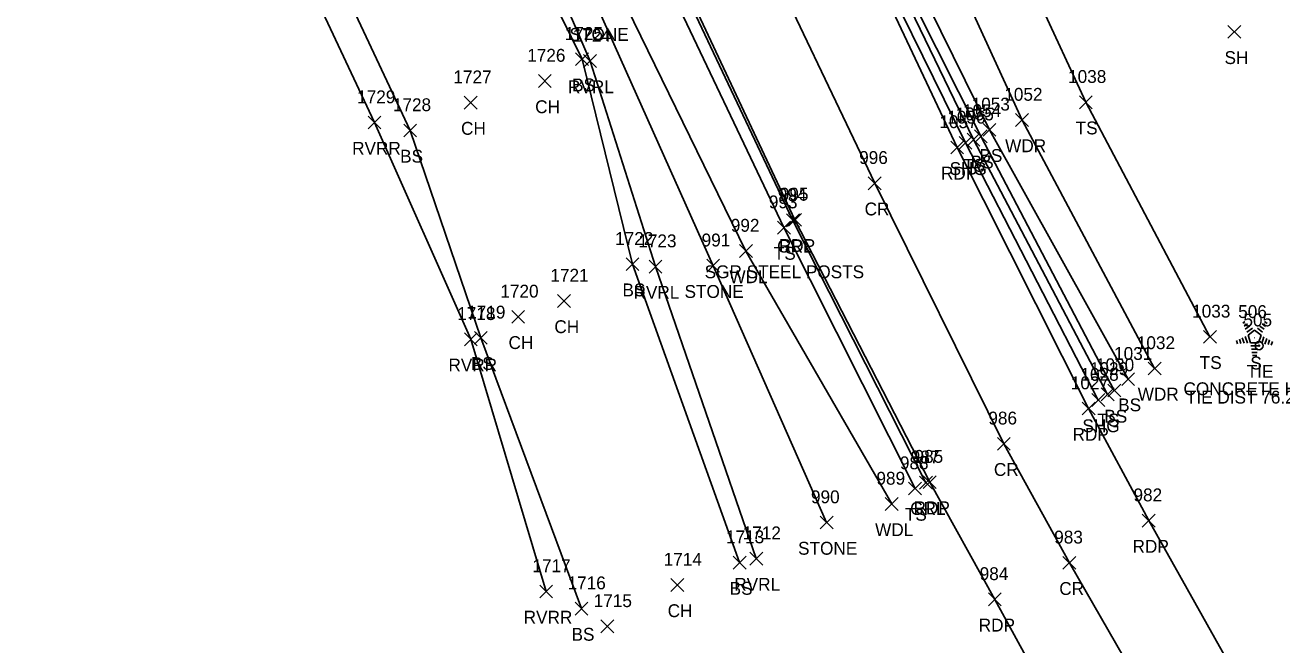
# Model space of a CAD drawing. Extents: x 1545627 to 1546562, y 571176 to 576667.
# Drawn here: x 1546177.9 to 1546373.5, y 571495.7 to 571592.1 of the extents above; entities that cross this region are included whole.
import ezdxf

# ---------------------------------------------------------------- set-up
doc = ezdxf.new("R2010")
doc.units = 0
for name, color, linetype in [('C_A', 7, 'Continuous'), ('C_C', 7, 'Continuous'), ('C_I', 7, 'Continuous'), ('CBP', 7, 'Continuous'), ('L_A', 7, 'Continuous'), ('L_C', 7, 'Continuous'), ('L_I', 7, 'Continuous'), ('L_TIC', 7, 'Continuous'), ('LASF', 7, 'Continuous'), ('LAWA', 7, 'Continuous'), ('LAWE', 7, 'Continuous'), ('LELB', 7, 'Continuous'), ('LTC', 7, 'Continuous'), ('P_A', 7, 'Continuous'), ('P_I', 7, 'Continuous'), ('P_TIC', 7, 'Continuous'), ('PET', 7, 'Continuous'), ('PRC', 7, 'Continuous'), ('PSU', 7, 'Continuous'), ('R_A', 7, 'Continuous'), ('R_C', 7, 'Continuous'), ('R_I', 7, 'Continuous'), ('R_TIC', 7, 'Continuous'), ('RGR', 7, 'Continuous')]:
    doc.layers.add(name, color=color, linetype=linetype)

msp = doc.modelspace()

# ---------------------------------------------------------------- linework, layer by layer
at = {"layer": 'CBP'}
for radius in [0.625, 0.0833]:
    msp.add_circle((1546369.94, 571542.21), radius, dxfattribs=at)
at = {"layer": 'L_TIC'}
for points in [[(1546365.08, 571590.01), (1546367.08, 571592.01)], [(1546367.08, 571590.01), (1546365.08, 571592.01)], [(1546263.55, 571585.76), (1546265.55, 571587.76)], [(1546265.55, 571585.76), (1546263.55, 571587.76)], [(1546264.8, 571585.47), (1546266.8, 571587.47)], [(1546266.8, 571585.47), (1546264.8, 571587.47)], [(1546257.77, 571582.37), (1546259.77, 571584.37)], [(1546259.77, 571582.37), (1546257.77, 571584.37)], [(1546246.23, 571579.01), (1546248.23, 571581.01)], [(1546248.23, 571579.01), (1546246.23, 571581.01)], [(1546341.98, 571579.07), (1546343.98, 571581.07)], [(1546343.98, 571579.07), (1546341.98, 571581.07)], [(1546332.05, 571576.3), (1546334.05, 571578.3)], [(1546334.05, 571576.3), (1546332.05, 571578.3)], [(1546231.25, 571575.91), (1546233.25, 571577.91)], [(1546233.25, 571575.91), (1546231.25, 571577.91)], [(1546236.8, 571574.68), (1546238.8, 571576.68)], [(1546238.8, 571574.68), (1546236.8, 571576.68)], [(1546326.97, 571574.78), (1546328.97, 571576.78)], [(1546328.97, 571574.78), (1546326.97, 571576.78)], [(1546324.48, 571573.25), (1546326.48, 571575.25)], [(1546326.48, 571573.25), (1546324.48, 571575.25)], [(1546325.62, 571573.77), (1546327.62, 571575.77)], [(1546327.62, 571573.77), (1546325.62, 571575.77)], [(1546294.99, 571559.57), (1546296.99, 571561.57)], [(1546296.99, 571559.57), (1546294.99, 571561.57)], [(1546289.07, 571555.93), (1546291.07, 571557.93)], [(1546291.07, 571555.93), (1546289.07, 571557.93)], [(1546271.41, 571553.88), (1546273.41, 571555.88)], [(1546273.41, 571553.88), (1546271.41, 571555.88)], [(1546275, 571553.51), (1546277, 571555.51)], [(1546277, 571553.51), (1546275, 571555.51)], [(1546283.96, 571553.64), (1546285.96, 571555.64)], [(1546285.96, 571553.64), (1546283.96, 571555.64)], [(1546260.76, 571548.16), (1546262.76, 571550.16)], [(1546262.76, 571548.16), (1546260.76, 571550.16)], [(1546253.62, 571545.69), (1546255.62, 571547.69)], [(1546255.62, 571545.69), (1546253.62, 571547.69)], [(1546246.25, 571542.2), (1546248.25, 571544.2)], [(1546248.25, 571542.2), (1546246.25, 571544.2)], [(1546247.81, 571542.43), (1546249.81, 571544.43)], [(1546249.81, 571542.43), (1546247.81, 571544.43)], [(1546361.29, 571542.58), (1546363.29, 571544.58)], [(1546363.29, 571542.58), (1546361.29, 571544.58)], [(1546352.68, 571537.67), (1546354.68, 571539.67)], [(1546354.68, 571537.67), (1546352.68, 571539.67)], [(1546348.57, 571536), (1546350.57, 571538)], [(1546350.57, 571536), (1546348.57, 571538)], [(1546345.37, 571533.64), (1546347.37, 571535.64)], [(1546347.37, 571533.64), (1546345.37, 571535.64)], [(1546346.4, 571534.24), (1546348.4, 571536.24)], [(1546348.4, 571534.24), (1546346.4, 571536.24)], [(1546315.39, 571518.99), (1546317.39, 571520.99)], [(1546317.39, 571518.99), (1546315.39, 571520.99)], [(1546311.75, 571516.59), (1546313.75, 571518.59)], [(1546313.75, 571516.59), (1546311.75, 571518.59)], [(1546301.63, 571513.7), (1546303.63, 571515.7)], [(1546303.63, 571513.7), (1546301.63, 571515.7)], [(1546290.68, 571508.09), (1546292.68, 571510.09)], [(1546292.68, 571508.09), (1546290.68, 571510.09)], [(1546288.09, 571507.47), (1546290.09, 571509.47)], [(1546290.09, 571507.47), (1546288.09, 571509.47)], [(1546278.39, 571503.99), (1546280.39, 571505.99)], [(1546280.39, 571503.99), (1546278.39, 571505.99)], [(1546257.96, 571502.98), (1546259.96, 571504.98)], [(1546259.96, 571502.98), (1546257.96, 571504.98)], [(1546263.48, 571500.32), (1546265.48, 571502.32)], [(1546265.48, 571500.32), (1546263.48, 571502.32)], [(1546267.49, 571497.55), (1546269.49, 571499.55)], [(1546269.49, 571497.55), (1546267.49, 571499.55)]]:
    msp.add_lwpolyline(points, dxfattribs=at)
at = {"layer": 'LASF'}
msp.add_lwpolyline([(1546302.63, 571514.7), (1546284.96, 571554.64), (1546267.07, 571594.62), (1546248.5, 571636.16), (1546232.58, 571676.44), (1546221.39, 571711.67), (1546206.12, 571743.52), (1546187.79, 571777.34), (1546173.69, 571810.79)], dxfattribs=at)
at = {"layer": 'LAWA'}
for points in [[(1546353.68, 571538.67), (1546333.05, 571577.3), (1546316.5, 571613.36), (1546304.35, 571639.71), (1546298.51, 571653.83), (1546282.89, 571690.9), (1546283.41, 571696.03), (1546272.32, 571717.42), (1546269.96, 571722.04), (1546267.97, 571732.31), (1546261.81, 571747.15), (1546257.75, 571780.48), (1546250.52, 571795.52), (1546235.49, 571816.76), (1546225.64, 571844.56)], [(1546312.75, 571517.59), (1546290.07, 571556.93), (1546270.45, 571597.1), (1546251.85, 571637.66), (1546235.21, 571678.3), (1546232.58, 571676.44)]]:
    msp.add_lwpolyline(points, dxfattribs=at)
at = {"layer": 'LAWE'}
for points in [[(1546291.68, 571509.09), (1546276, 571554.51), (1546265.8, 571586.47), (1546246.73, 571630.75), (1546234.82, 571659.95), (1546216.56, 571711.52), (1546198.01, 571746.58), (1546176.48, 571789.7), (1546167.29, 571818.28), (1546149.73, 571861.96), (1546132.38, 571905.18), (1546121.26, 571957.17), (1546118.8, 571996.68)], [(1546258.96, 571503.98), (1546247.25, 571543.2), (1546232.25, 571576.91), (1546212.48, 571618.99), (1546196.14, 571656.31), (1546182.65, 571695.75), (1546160.61, 571737.45), (1546138.23, 571773.59), (1546130.29, 571811.19), (1546113.32, 571843.26), (1546096.49, 571860.06), (1546088.58, 571875.57), (1546087.04, 571900.32), (1546085.16, 571952.92), (1546079.44, 571966.95), (1546077.79, 571985.49)]]:
    msp.add_lwpolyline(points, dxfattribs=at)
at = {"layer": 'LELB'}
for points in [[(1546347.4, 571535.24), (1546326.62, 571574.77), (1546309.35, 571609.13), (1546297.64, 571636.43), (1546292.79, 571646.22), (1546275.73, 571689.36), (1546263.63, 571715.11), (1546250.32, 571751.35), (1546233.4, 571797.16), (1546220.82, 571841.74), (1546218.61, 571853), (1546198.39, 571897.18), (1546185.1, 571947.88), (1546175.65, 571989.22), (1546174.94, 572003.26), (1546174.78, 572026.81), (1546167.55, 572047.44), (1546164.76, 572064.39), (1546160.42, 572092.89), (1546150.12, 572129.23)], [(1546346.37, 571534.64), (1546325.48, 571574.25), (1546308.89, 571608.63), (1546296.21, 571635.99), (1546273.97, 571687.64), (1546262.69, 571714.72), (1546248.75, 571750.39), (1546231.96, 571796.63), (1546217.3, 571838.7), (1546210.36, 571854.99), (1546196.65, 571897), (1546182.1, 571946.81), (1546169.64, 571995.56), (1546168.24, 572028.13), (1546158.04, 572044.97), (1546148.17, 572086.53), (1546140.64, 572120.6)], [(1546316.39, 571519.99), (1546295.99, 571560.57), (1546277.23, 571599.95), (1546257.92, 571640.86), (1546240.42, 571680.68), (1546227.25, 571713.56), (1546212.6, 571746.96), (1546199.61, 571780.81), (1546186.37, 571815.41), (1546174.93, 571851.82), (1546162.84, 571891.38), (1546151.94, 571927.81), (1546142.36, 571967.05), (1546132.26, 572008.4), (1546126.74, 572032.68), (1546118.89, 572071.99), (1546116.87, 572083.76)], [(1546289.09, 571508.47), (1546272.41, 571554.88), (1546264.55, 571586.76), (1546244.35, 571627.87), (1546230.42, 571657.81), (1546213.76, 571710.05), (1546197.12, 571744.15), (1546174.21, 571790.13), (1546160.91, 571814.7), (1546145.83, 571859.21), (1546131.62, 571904.03), (1546118.44, 571956.95), (1546115.97, 571995.99), (1546108.78, 572035.92), (1546103.73, 572068.58)], [(1546264.48, 571501.32), (1546248.81, 571543.43), (1546237.8, 571575.68), (1546217.63, 571618.65), (1546201.94, 571655.46), (1546187.64, 571696.37), (1546165.93, 571736.68), (1546143.43, 571776.5), (1546133.35, 571812.72), (1546115.39, 571843.89), (1546097.02, 571861.67), (1546090.93, 571875.32), (1546090.22, 571893.11)], [(1546362.29, 571543.58), (1546342.98, 571580.07), (1546328.32, 571611.66), (1546309.49, 571653.11), (1546294.54, 571692.89), (1546292.56, 571714.76), (1546278.25, 571725.92)], [(1546349.57, 571537), (1546327.97, 571575.78), (1546310.96, 571610.3), (1546300.23, 571637.22)]]:
    msp.add_lwpolyline(points, dxfattribs=at)
at = {"layer": 'LTC'}
for p, q in [((1546367.39, 571545.71), (1546367.74, 571545.97)), ((1546367.6, 571545.25), (1546368.12, 571545.63)), ((1546367.8, 571544.78), (1546368.51, 571545.29)), ((1546368.01, 571544.32), (1546368.89, 571544.95)), ((1546369.67, 571544.91), (1546370.48, 571544.32)), ((1546370.04, 571545.26), (1546370.72, 571544.76)), ((1546370.41, 571545.61), (1546370.96, 571545.21)), ((1546370.78, 571545.95), (1546371.2, 571545.65)), ((1546366.42, 571542.99), (1546366.57, 571542.52)), ((1546366.87, 571543.21), (1546367.09, 571542.56)), ((1546367.33, 571543.43), (1546367.6, 571542.59)), ((1546367.78, 571543.64), (1546368.12, 571542.62)), ((1546368.24, 571543.86), (1546369.25, 571544.6)), ((1546368.24, 571543.86), (1546368.63, 571542.67)), ((1546369.25, 571544.6), (1546370.25, 571543.87)), ((1546370.25, 571543.87), (1546369.86, 571542.67)), ((1546370.69, 571543.6), (1546370.35, 571542.56)), ((1546371.13, 571543.35), (1546370.84, 571542.46)), ((1546371.57, 571543.1), (1546371.34, 571542.37)), ((1546372.02, 571542.85), (1546371.83, 571542.27)), ((1546369.86, 571542.67), (1546368.63, 571542.67)), ((1546369.82, 571542.17), (1546368.67, 571542.17)), ((1546369.73, 571541.67), (1546368.75, 571541.67)), ((1546369.65, 571541.17), (1546368.82, 571541.17)), ((1546369.57, 571540.67), (1546368.89, 571540.67))]:
    msp.add_line(p, q, dxfattribs=at)
at = {"layer": 'P_TIC'}
for points in [[(1546323.24, 571572.75), (1546325.24, 571574.75)], [(1546325.24, 571572.75), (1546323.24, 571574.75)], [(1546321.94, 571572.04), (1546323.94, 571574.04)], [(1546323.94, 571572.04), (1546321.94, 571574.04)], [(1546309.11, 571566.47), (1546311.11, 571568.47)], [(1546311.11, 571566.47), (1546309.11, 571568.47)], [(1546296.7, 571560.78), (1546298.7, 571562.78)], [(1546298.7, 571560.78), (1546296.7, 571562.78)], [(1546342.41, 571531.43), (1546344.41, 571533.43)], [(1546344.41, 571531.43), (1546342.41, 571533.43)], [(1546343.91, 571532.75), (1546345.91, 571534.75)], [(1546345.91, 571532.75), (1546343.91, 571534.75)], [(1546329.22, 571525.95), (1546331.22, 571527.95)], [(1546331.22, 571525.95), (1546329.22, 571527.95)], [(1546317.67, 571519.99), (1546319.67, 571521.99)], [(1546319.67, 571519.99), (1546317.67, 571521.99)], [(1546351.76, 571514), (1546353.76, 571516)], [(1546353.76, 571514), (1546351.76, 571516)], [(1546339.41, 571507.44), (1546341.41, 571509.44)], [(1546341.41, 571507.44), (1546339.41, 571509.44)], [(1546327.81, 571501.75), (1546329.81, 571503.75)], [(1546329.81, 571501.75), (1546327.81, 571503.75)]]:
    msp.add_lwpolyline(points, dxfattribs=at)
at = {"layer": 'PET'}
for points in [[(1546536.21, 571181.01), (1546508.17, 571223.67), (1546475.69, 571271.66), (1546448.41, 571311.32), (1546419.18, 571354.19), (1546394.92, 571390.86), (1546367.78, 571434.2), (1546346.92, 571469.65), (1546328.81, 571502.75), (1546318.67, 571520.99), (1546297.7, 571561.78), (1546279.07, 571601.48), (1546260.13, 571643.3), (1546242.96, 571682.18), (1546229.29, 571714.28), (1546215.95, 571747.93), (1546202.6, 571782.08), (1546189.82, 571816.62), (1546177.58, 571852.76), (1546165.76, 571891.53), (1546154.55, 571928.81), (1546144.5, 571967.92), (1546134.66, 572009.13)], [(1546559.08, 571194.5), (1546529.75, 571240.45), (1546499.79, 571284.88), (1546470.8, 571327.72), (1546443.13, 571367.68), (1546417.68, 571406.9), (1546392.95, 571446.31), (1546370.2, 571483.99), (1546352.76, 571515), (1546343.41, 571532.43), (1546322.94, 571573.04), (1546306.85, 571607.13), (1546293.98, 571634.56), (1546271.4, 571685.96), (1546259.46, 571713.47), (1546245.43, 571748.53), (1546227.67, 571795.22), (1546213.04, 571834.88), (1546205.18, 571857.76), (1546192.7, 571896.53), (1546178.72, 571945.47), (1546165.66, 571996.1)]]:
    msp.add_lwpolyline(points, dxfattribs=at)
at = {"layer": 'PRC'}
msp.add_lwpolyline([(1546547.34, 571187.72), (1546518.74, 571231.86), (1546487.31, 571278.43), (1546459.33, 571318.89), (1546430.57, 571360.77), (1546405.96, 571398.26), (1546380.25, 571440.1), (1546358.53, 571476.99), (1546340.41, 571508.44), (1546330.22, 571526.95), (1546310.11, 571567.47), (1546291.29, 571606.95), (1546272.42, 571649.01), (1546255.63, 571687.66), (1546242.53, 571719.45), (1546229.29, 571753.1), (1546216.08, 571786.74), (1546203.35, 571821.01), (1546191.26, 571856.19), (1546178.74, 571896.13), (1546167.5, 571932.69), (1546157.43, 571971.54), (1546147.89, 572011.79)], dxfattribs=at)
at = {"layer": 'PSU'}
msp.add_lwpolyline([(1546344.91, 571533.75), (1546324.24, 571573.75), (1546307.57, 571607.61), (1546295.25, 571635.34), (1546272.39, 571686.56), (1546261.3, 571714.23), (1546246.81, 571749.3), (1546229.82, 571796.03), (1546214.93, 571836.38), (1546208.22, 571856.11), (1546194.62, 571896.65), (1546180.08, 571945.81), (1546167.4, 571995.97), (1546161.66, 572024.84), (1546155.58, 572044.54)], dxfattribs=at)
at = {"layer": 'R_TIC'}
for points in [[(1546296.39, 571560.7), (1546298.39, 571562.7)], [(1546298.39, 571560.7), (1546296.39, 571562.7)], [(1546317.09, 571519.89), (1546319.09, 571521.89)], [(1546319.09, 571519.89), (1546317.09, 571521.89)]]:
    msp.add_lwpolyline(points, dxfattribs=at)
at = {"layer": 'RGR'}
msp.add_lwpolyline([(1546318.09, 571520.89), (1546297.39, 571561.7), (1546278.61, 571601.26), (1546259.67, 571643.05), (1546242.43, 571682.09), (1546228.78, 571714.21), (1546215.19, 571747.99), (1546202.24, 571781.5), (1546189.29, 571816.51), (1546177.18, 571852.71), (1546165.01, 571891.35), (1546154.15, 571928.78), (1546143.68, 571967.8), (1546133.91, 572008.79), (1546128.63, 572033), (1546121.13, 572073.3), (1546118.95, 572085.97)], dxfattribs=at)

# ---------------------------------------------------------------- texts
at = {"layer": 'C_A'}
msp.add_text('TIE', height=2, dxfattribs=at).set_placement((1546368.02, 571537.21))
at = {"layer": 'C_C'}
msp.add_text('TIE DIST 76.215', height=2, dxfattribs=at).set_placement((1546358.54, 571533.21))
at = {"layer": 'C_I'}
msp.add_text('505', height=2, dxfattribs=at).set_placement((1546367.5, 571545.21))
at = {"layer": 'L_A'}
for s, p in [('STONE', (1546262.61, 571589.62)), ('SH', (1546364.56, 571586.01)), ('RVRL', (1546262.37, 571581.47)), ('BS', (1546263, 571581.76)), ('CH', (1546257.26, 571578.37)), ('CH', (1546245.72, 571575.01)), ('TS', (1546341.39, 571575.07)), ('WDR', (1546330.41, 571572.3)), ('RVRR', (1546228.77, 571571.91)), ('BS', (1546236.24, 571570.68)), ('BS', (1546326.41, 571570.78)), ('TS', (1546323.89, 571569.25)), ('BS', (1546325.06, 571569.77)), ('TS', (1546294.4, 571555.57)), ('WDL', (1546287.49, 571551.93)), ('BS', (1546270.85, 571549.88)), ('RVRL', (1546272.57, 571549.51)), ('STONE', (1546280.51, 571549.64)), ('CH', (1546260.25, 571544.16)), ('CH', (1546253.11, 571541.69)), ('RVRR', (1546243.76, 571538.2)), ('BS', (1546247.25, 571538.43)), ('TS', (1546360.7, 571538.58)), ('S', (1546368.58, 571538.51)), ('WDR', (1546351.05, 571533.67)), ('BS', (1546348.01, 571532)), ('TS', (1546344.78, 571529.64)), ('BS', (1546345.85, 571530.24)), ('TS', (1546314.8, 571514.99)), ('WDL', (1546310.17, 571512.59)), ('STONE', (1546298.18, 571509.7)), ('RVRL', (1546288.25, 571504.09)), ('BS', (1546287.53, 571503.47)), ('CH', (1546277.88, 571499.99)), ('RVRR', (1546255.47, 571498.98)), ('BS', (1546262.92, 571496.32))]:
    msp.add_text(s, height=2, dxfattribs=at).set_placement(p)
at = {"layer": 'L_C'}
msp.add_text('CONCRETE HWY', height=2, dxfattribs=at).set_placement((1546358.17, 571534.51))
at = {"layer": 'L_I'}
for s, p in [('1725', (1546261.86, 571589.76)), ('1724', (1546263.11, 571589.47)), ('1726', (1546256.02, 571586.37)), ('1727', (1546244.53, 571583.01)), ('1038', (1546340.21, 571583.07)), ('1052', (1546330.28, 571580.3)), ('1729', (1546229.55, 571579.91)), ('1728', (1546235.11, 571578.68)), ('1053', (1546325.2, 571578.78)), ('1055', (1546322.71, 571577.25)), ('1054', (1546323.85, 571577.77)), ('993', (1546293.63, 571563.57)), ('992', (1546287.71, 571559.93)), ('1722', (1546269.71, 571557.88)), ('1723', (1546273.31, 571557.51)), ('991', (1546283.17, 571557.64)), ('1721', (1546259.63, 571552.16)), ('1720', (1546251.84, 571549.69)), ('1718', (1546245.13, 571546.2)), ('1719', (1546246.68, 571546.43)), ('1033', (1546359.52, 571546.58)), ('506', (1546366.69, 571546.51)), ('1032', (1546350.91, 571541.67)), ('1031', (1546347.37, 571540)), ('1029', (1546343.6, 571537.64)), ('1030', (1546344.55, 571538.24)), ('988', (1546314.03, 571522.99)), ('989', (1546310.38, 571520.59)), ('990', (1546300.19, 571517.7)), ('1713', (1546286.96, 571511.47)), ('1712', (1546289.56, 571512.09)), ('1714', (1546277.27, 571507.99)), ('1717', (1546256.83, 571506.98)), ('1716', (1546262.3, 571504.32)), ('1715', (1546266.37, 571501.55))]:
    msp.add_text(s, height=2, dxfattribs=at).set_placement(p)
at = {"layer": 'LTC'}
msp.add_text('.', height=1.04, rotation=270, dxfattribs=at).set_placement((1546369.13, 571543.61))
at = {"layer": 'P_A'}
for s, p in [('SHG', (1546321.77, 571568.75)), ('RDP', (1546320.43, 571568.04)), ('CR', (1546308.54, 571562.47)), ('RDP', (1546295.19, 571556.78)), ('RDP', (1546340.9, 571527.43)), ('SHG', (1546342.44, 571528.75)), ('CR', (1546328.66, 571521.95)), ('RDP', (1546316.16, 571515.99)), ('RDP', (1546350.24, 571510)), ('CR', (1546338.84, 571503.44)), ('RDP', (1546326.3, 571497.75))]:
    msp.add_text(s, height=2, dxfattribs=at).set_placement(p)
at = {"layer": 'P_I'}
for s, p in [('1057', (1546320.17, 571576.04)), ('1056', (1546321.41, 571576.75)), ('996', (1546307.69, 571570.47)), ('995', (1546295.34, 571564.78)), ('1027', (1546340.64, 571535.43)), ('1028', (1546342.14, 571536.75)), ('986', (1546327.8, 571529.95)), ('985', (1546316.31, 571523.99)), ('982', (1546350.39, 571518)), ('983', (1546338.05, 571511.44)), ('984', (1546326.45, 571505.75))]:
    msp.add_text(s, height=2, dxfattribs=at).set_placement(p)
at = {"layer": 'R_A'}
for p in [(1546294.93, 571556.7), (1546315.63, 571515.89)]:
    msp.add_text('GRL', height=2, dxfattribs=at).set_placement(p)
at = {"layer": 'R_C'}
msp.add_text('SGR STEEL POSTS', height=2, dxfattribs=at).set_placement((1546283.64, 571552.7))
at = {"layer": 'R_I'}
for s, p in [('994', (1546295.03, 571564.7)), ('987', (1546315.72, 571523.89))]:
    msp.add_text(s, height=2, dxfattribs=at).set_placement(p)

doc.saveas('drawing.dxf')
